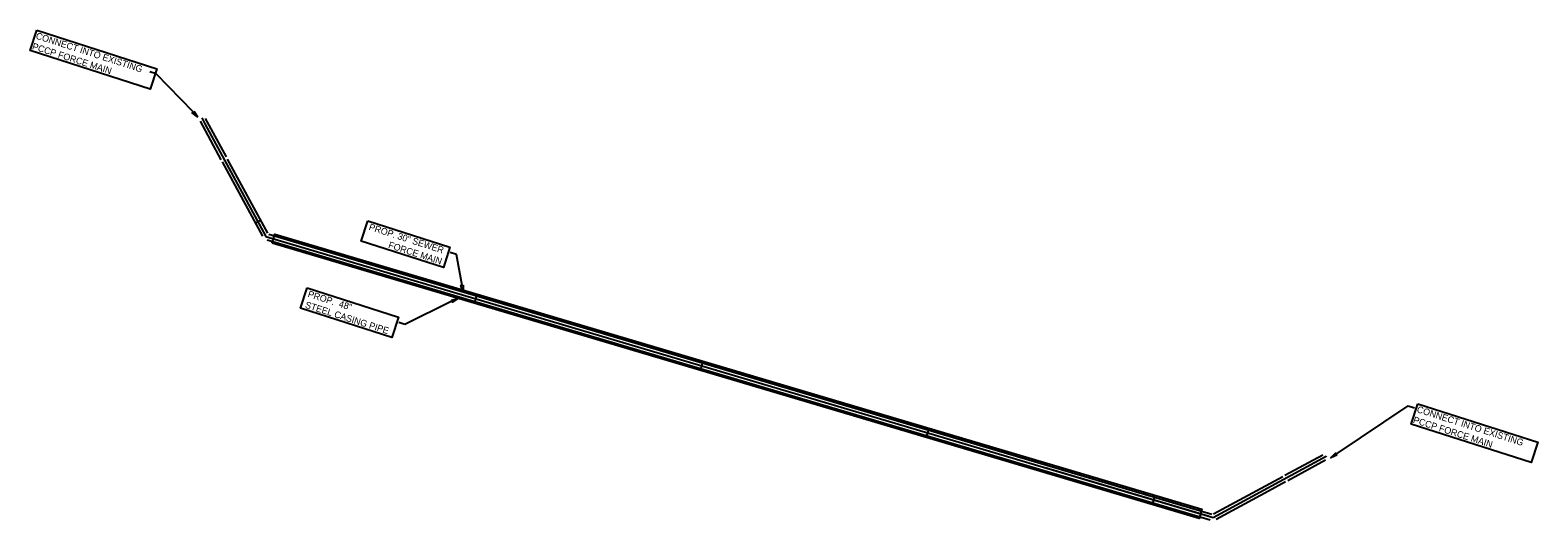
# Model space of a CAD drawing. Extents: x 1961446 to 1965364, y 798002 to 798458.
# Drawn here: x 1961446 to 1962085, y 798251 to 798458 of the extents above; entities that cross this region are included whole.
import ezdxf

# ---------------------------------------------------------------- set-up
doc = ezdxf.new("R2010")
doc.units = 0
for name, color, linetype in [('_C3D-PRSR-PIPE-NEW 30 FM', 7, 'Continuous'), ('C-ALGN-CNTR', 7, 'Continuous'), ('C-ALGN-DATA', 7, 'Continuous'), ('C-DOMW-MAIN-PIPE', 7, 'Continuous'), ('C-SSWR-FMAN-PIPE', 7, 'Continuous'), ('G-ANNO-NOTE', 7, 'Continuous'), ('TEMPORARY EASEMENT', 7, 'Continuous')]:
    doc.layers.add(name, color=color, linetype=linetype)

msp = doc.modelspace()

# ---------------------------------------------------------------- linework, layer by layer
at = {"layer": '_C3D-PRSR-PIPE-NEW 30 FM'}
msp.add_lwpolyline([(1961548.16, 798367.96), (1961549.3, 798371.79), (1961942.49, 798255.11), (1961941.35, 798251.27)], close=True, dxfattribs=at)
at = {"layer": 'C-ALGN-CNTR'}
for points in [[(1961518.31, 798421.09), (1961519.7, 798418.54)], [(1961519.7, 798418.54), (1961545.58, 798370.81)], [(1961545.58, 798370.81), (1961947.26, 798251.6)], [(1961947.26, 798251.6), (1961995.17, 798277.59)], [(1961995.17, 798277.59), (1961995.3, 798277.55)]]:
    msp.add_lwpolyline(points, dxfattribs=at)
at = {"layer": 'C-ALGN-DATA'}
for points in [[(1961540.83, 798376.43), (1961543.47, 798377.86)], [(1961634.12, 798342.97), (1961634.97, 798345.85)], [(1961729.99, 798314.52), (1961730.84, 798317.39)], [(1961825.85, 798286.07), (1961826.71, 798288.94)], [(1961921.72, 798257.62), (1961922.58, 798260.49)]]:
    msp.add_lwpolyline(points, dxfattribs=at)
at = {"layer": 'C-DOMW-MAIN-PIPE'}
for points in [[(1961517.63, 798419.73), (1961526.49, 798403.37)], [(1961519.83, 798420.92), (1961528.69, 798404.56)], [(1961526.99, 798402.46), (1961544.04, 798370.97)], [(1961529.18, 798403.65), (1961546.24, 798372.16)]]:
    msp.add_lwpolyline(points, dxfattribs=at)
at = {"layer": 'C-SSWR-FMAN-PIPE'}
for points in [[(1961546.08, 798369.39), (1961946.06, 798250.64)], [(1961546.79, 798371.79), (1961946.77, 798253.04)], [(1961977.71, 798269.54), (1961993.81, 798278.26)], [(1961978.9, 798267.34), (1961995, 798276.06)], [(1961969.55, 798265.11), (1961976.81, 798269.05)], [(1961970.74, 798262.92), (1961978, 798266.85)], [(1961947.43, 798253.13), (1961969.55, 798265.11)], [(1961948.62, 798250.93), (1961970.74, 798262.92)]]:
    msp.add_lwpolyline(points, dxfattribs=at)
at = {"layer": 'G-ANNO-NOTE'}
for points in [[(1961448.33, 798458.32), (1961499.29, 798441.97), (1961496.53, 798433.35), (1961445.56, 798449.7)], [(1961514.97, 798423.93), (1961516.58, 798421.58), (1961514.29, 798423.28)], [(1961588.74, 798377.5), (1961623.61, 798366.31), (1961620.84, 798357.69), (1961585.97, 798368.88)], [(1961629.2, 798350.16), (1961629.23, 798347.31), (1961628.28, 798350)], [(1961563.02, 798349.03), (1961601.75, 798336.6), (1961598.99, 798327.98), (1961560.25, 798340.41)], [(1961624.25, 798343.74), (1961626.98, 798344.57), (1961624.66, 798342.9)], [(1962034.03, 798299.91), (1962084.99, 798283.56), (1962082.22, 798274.94), (1962031.26, 798291.29)], [(1961999.73, 798278.14), (1961997.13, 798276.96), (1961999.21, 798278.92)]]:
    msp.add_lwpolyline(points, close=True, dxfattribs=at)
for points in [[(1961499.01, 798439.82), (1961496.33, 798440.68)], [(1961514.63, 798423.61), (1961499.01, 798439.82)], [(1961626.39, 798363.18), (1961623.71, 798364.04)], [(1961628.74, 798350.08), (1961626.39, 798363.18)], [(1961624.46, 798343.32), (1961604.54, 798333.47)], [(1961604.54, 798333.47), (1961601.86, 798334.32)], [(1961999.47, 798278.53), (1962029.94, 798298.98)], [(1962029.94, 798298.98), (1962032.62, 798298.12)]]:
    msp.add_lwpolyline(points, dxfattribs=at)
at = {"layer": 'TEMPORARY EASEMENT'}
msp.add_lwpolyline([(1961945.19, 798252.2), (1961875.99, 798272.7)], dxfattribs=at)

# ---------------------------------------------------------------- texts
at = {"layer": 'G-ANNO-NOTE'}
for s, height, p in [('PCCP FORCE MAIN', 2.8125, (1961446.18, 798450.29)), ('CONNECT INTO EXISTING', 2.8125, (1961447.72, 798454.77)), ('PROP. 30" SEWER', 2.8125, (1961588.97, 798373.68)), ('FORCE MAIN', 2.812, (1961597.22, 798366.06)), ('STEEL CASING PIPE', 2.8125, (1961561.95, 798340.65)), ('PROP.  48"', 2.812, (1961563.08, 798345.26)), ('CONNECT INTO EXISTING', 2.8125, (1962033.42, 798296.36)), ('PCCP FORCE MAIN', 2.8125, (1962031.87, 798291.88))]:
    msp.add_text(s, height=height, rotation=342.21, dxfattribs=at).set_placement(p)

doc.saveas('drawing.dxf')
